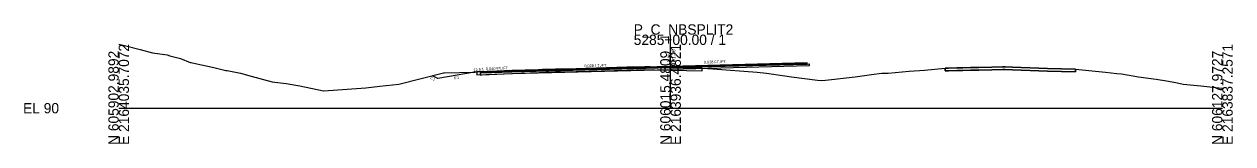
# Model space of a CAD drawing. Extents: x -26 to 1303, y -10 to 12038.
# Drawn here: x -25.7 to 302.8, y 2990.3 to 3022.8 of the extents above; entities that cross this region are included whole.
import ezdxf

# ---------------------------------------------------------------- set-up
doc = ezdxf.new("R2010")
doc.units = 0
for name, color, linetype in [('RD_GPK_XS_Cell', 7, 'Continuous'), ('RD_XS_Base', 7, 'Continuous'), ('RD_XS_ExGround', 7, 'Continuous'), ('RD_XS_ExPaveRet', 7, 'Continuous'), ('RD_XS_Greenside', 7, 'Continuous'), ('RD_XS_Pave', 7, 'Continuous'), ('RD_XS_PaveOvlay_CP', 7, 'Continuous'), ('RD_XS_TieSlope', 7, 'Continuous'), ('RD_XS_TX_Elev_EX', 7, 'Continuous'), ('RD_XS_TX_Elev_PR', 7, 'Continuous'), ('RD_XS_TX_ShdSlope', 7, 'Continuous'), ('RD_XS_TX_Slope', 7, 'Continuous')]:
    doc.layers.add(name, color=color, linetype=linetype)

msp = doc.modelspace()

# ---------------------------------------------------------------- linework, layer by layer
at = {"layer": 'RD_GPK_XS_Cell'}
for p, q in [((150, 3000), (150, 3020)), ((0, 3000), (150, 3000)), ((150, 3000), (300, 3000))]:
    msp.add_line(p, q, dxfattribs=at)
at = {"layer": 'RD_XS_Base'}
for p, q in [((98.73, 3009.59), (98.23, 3009.57)), ((98.23, 3009.57), (98.23, 3009.57)), ((98.23, 3009.57), (98.23, 3009.07)), ((106.83, 3009.92), (98.73, 3009.59)), ((98.73, 3009.59), (98.73, 3009.59)), ((98.73, 3009.09), (106.83, 3009.42)), ((150, 3011.04), (106.83, 3009.92)), ((106.83, 3009.42), (150, 3010.54)), ((138, 3010.73), (138, 3010.73)), ((138, 3010.23), (138, 3010.23)), ((150, 3011.04), (187.66, 3012.02)), ((187.66, 3011.52), (150, 3010.54)), ((150, 3010.54), (150, 3011.2)), ((150, 3011.2), (150, 3011.2)), ((150, 3011.2), (150, 3011.2)), ((150, 3011.2), (150, 3011.04)), ((150, 3011.04), (150, 3011.04)), ((150, 3010.54), (150, 3011.04)), ((150, 3011.04), (150, 3011.04)), ((150, 3011.04), (150, 3011.04)), ((150, 3010.54), (150, 3010.54)), ((174, 3011.66), (174, 3011.66)), ((174, 3011.66), (174, 3011.66)), ((174, 3011.16), (174, 3011.16)), ((174, 3011.16), (174, 3011.16)), ((187.16, 3012.01), (187.16, 3012.01)), ((187.66, 3012.02), (187.66, 3011.52)), ((187.66, 3011.99), (187.66, 3011.99)), ((98.23, 3009.07), (98.73, 3009.09)), ((98.73, 3009.09), (98.73, 3009.09))]:
    msp.add_line(p, q, dxfattribs=at)
at = {"layer": 'RD_XS_ExGround'}
msp.add_lwpolyline([(0, 3017.36), (1.91, 3016.98), (5.88, 3015.95), (9.16, 3015.07), (13.16, 3014.48), (13.88, 3014.25), (16.81, 3013.48), (19.46, 3012.46), (19.74, 3012.39), (20.41, 3012.24), (25.87, 3011.07), (29.15, 3010.2), (29.46, 3010.21), (33.12, 3009.48), (36, 3008.71), (41.73, 3007.12), (45.53, 3006.7), (49.2, 3006.07), (55.65, 3004.71), (55.7, 3004.69), (55.77, 3004.7), (67.14, 3005.51), (70.97, 3005.98), (76.17, 3006.54), (88.27, 3009.57), (88.48, 3009.62), (96.82, 3009.83), (97.37, 3009.85), (97.38, 3009.85), (114.31, 3010.46), (115.19, 3010.48), (116.15, 3010.5), (118.69, 3010.59), (124.37, 3010.74), (138.12, 3011.12), (143.03, 3011.24), (143.04, 3011.22), (143.05, 3011.21), (143.18, 3011.22), (144.49, 3011.22), (145.76, 3011.19), (158.6, 3010.87), (161.53, 3010.71), (173.53, 3009.77), (176.08, 3009.52), (181.07, 3008.8), (182.92, 3008.5), (189.93, 3007.66), (191.01, 3007.51), (192.11, 3007.66), (200.2, 3008.5), (204.6, 3009.12), (207.45, 3009.48), (209.2, 3009.54), (214.85, 3010.06), (219.03, 3010.35), (224.65, 3010.86), (227.84, 3010.96), (230.72, 3011.04), (233.78, 3011.08), (240.24, 3011.23), (240.99, 3011.23), (252.51, 3010.83), (260.05, 3010.59), (268.19, 3009.83), (271.33, 3009.45), (272.56, 3009.33), (277.18, 3008.5), (282.01, 3007.85), (284.79, 3007.45), (287.39, 3006.95), (289.37, 3006.5), (294.12, 3006.06), (299.81, 3005.4), (300, 3005.44)], dxfattribs=at)
at = {"layer": 'RD_XS_ExPaveRet'}
for points in [[(158.6, 3010.87), (158.6, 3010.87), (145.76, 3011.19), (145.76, 3011.19), (144.49, 3011.22), (143.18, 3011.22), (143.18, 3011.22), (143.05, 3011.21), (143.05, 3011.21), (143.04, 3011.22), (143.03, 3011.24), (143.03, 3011.24), (143.03, 3011.24), (138.12, 3011.12), (138.12, 3011.12), (124.37, 3010.74), (124.37, 3010.74), (124.37, 3010.74), (118.69, 3010.59), (118.69, 3010.59), (116.15, 3010.5), (115.19, 3010.48), (114.31, 3010.46), (114.31, 3010.46), (114.31, 3010.46), (97.38, 3009.85), (97.38, 3009.85), (97.38, 3009.85), (97.37, 3009.85), (97.37, 3009.85), (97.37, 3009.85), (97.37, 3009.1), (97.37, 3009.1), (97.38, 3009.1), (97.38, 3009.1), (97.38, 3009.1), (114.31, 3009.71), (114.31, 3009.71), (114.31, 3009.71), (115.19, 3009.73), (116.15, 3009.75), (118.69, 3009.84), (118.69, 3009.84), (124.37, 3009.99), (124.37, 3009.99), (124.37, 3009.99), (138.12, 3010.37), (138.12, 3010.37), (143.03, 3010.49), (143.03, 3010.49), (143.03, 3010.49), (143.04, 3010.47), (143.05, 3010.46), (143.05, 3010.46), (143.18, 3010.47), (143.18, 3010.47), (144.49, 3010.47), (145.76, 3010.44), (145.76, 3010.44), (158.6, 3010.12), (158.6, 3010.12), (158.6, 3010.12), (158.6, 3010.87), (158.6, 3010.87), (158.6, 3010.87)], [(158.6, 3010.87), (145.76, 3011.19), (144.49, 3011.22), (143.18, 3011.22), (143.05, 3011.21), (143.04, 3011.22), (143.03, 3011.24), (138.12, 3011.12), (124.37, 3010.74), (118.69, 3010.59), (116.15, 3010.5), (115.19, 3010.48), (114.31, 3010.46), (97.38, 3009.85), (97.37, 3009.85), (97.37, 3009.85), (97.37, 3009.1), (97.37, 3009.1), (97.38, 3009.1), (114.31, 3009.71), (115.19, 3009.73), (116.15, 3009.75), (118.69, 3009.84), (124.37, 3009.99), (138.12, 3010.37), (143.03, 3010.49), (143.04, 3010.47), (143.05, 3010.46), (143.18, 3010.47), (144.49, 3010.47), (145.76, 3010.44), (158.6, 3010.12), (158.6, 3010.12), (158.6, 3010.87), (158.6, 3010.87)], [(256.3, 3010.71), (260.05, 3010.59), (260.05, 3010.03), (260.05, 3009.84), (256.3, 3009.96), (252.51, 3010.08), (242.92, 3010.41), (240.99, 3010.48), (240.38, 3010.48), (240.24, 3010.48), (237.32, 3010.41), (233.78, 3010.33), (231.53, 3010.3), (229.46, 3010.24), (228.64, 3010.23), (227.84, 3010.21), (225.58, 3010.14), (224.65, 3010.11), (224.65, 3010.11), (224.65, 3010.11), (224.65, 3010.43), (224.65, 3010.86), (224.65, 3010.86), (224.65, 3010.86), (225.58, 3010.89), (227.84, 3010.96), (228.64, 3010.98), (229.46, 3010.99), (231.53, 3011.05), (233.78, 3011.08), (237.32, 3011.16), (240.24, 3011.23), (240.38, 3011.23), (240.99, 3011.23), (242.92, 3011.16), (252.51, 3010.83), (256.3, 3010.71)], [(252.51, 3010.83), (242.92, 3011.16), (240.99, 3011.23), (240.38, 3011.23), (240.24, 3011.23), (237.32, 3011.16), (233.78, 3011.08), (231.53, 3011.05), (229.46, 3010.99), (228.64, 3010.98), (227.84, 3010.96), (225.58, 3010.89), (224.65, 3010.86), (224.65, 3010.86), (224.65, 3010.43), (224.65, 3010.11)], [(224.65, 3010.11), (225.58, 3010.14), (227.84, 3010.21), (228.64, 3010.23), (229.46, 3010.24), (231.53, 3010.3), (233.78, 3010.33), (237.32, 3010.41), (240.24, 3010.48), (240.38, 3010.48), (240.99, 3010.48), (242.92, 3010.41), (252.51, 3010.08), (256.3, 3009.96), (260.05, 3009.84), (260.05, 3010.03), (260.05, 3010.59), (256.3, 3010.71), (252.51, 3010.83)], [(224.65, 3010.11), (224.65, 3010.11)]]:
    msp.add_lwpolyline(points, dxfattribs=at)
at = {"layer": 'RD_XS_Greenside'}
for p, q in [((96.73, 3009.75), (86.73, 3008.08)), ((86.73, 3008.08), (85.27, 3008.82))]:
    msp.add_line(p, q, dxfattribs=at)
at = {"layer": 'RD_XS_Pave'}
for p, q in [((106.83, 3010.24), (98.73, 3009.91)), ((98.73, 3009.75), (106.83, 3010.08)), ((106.83, 3010.08), (98.73, 3009.75)), ((98.73, 3009.59), (106.83, 3009.92)), ((98.73, 3009.91), (98.73, 3009.91)), ((98.73, 3009.91), (98.73, 3009.75)), ((98.73, 3009.75), (98.73, 3009.75)), ((98.73, 3009.75), (98.73, 3009.59)), ((150, 3011.36), (106.83, 3010.24)), ((106.83, 3010.08), (150, 3011.2)), ((150, 3011.2), (106.83, 3010.08)), ((106.83, 3009.92), (150, 3011.04)), ((138, 3011.05), (138, 3011.05)), ((138, 3010.89), (138, 3010.89)), ((138, 3010.89), (138, 3010.89)), ((138, 3010.73), (138, 3010.73)), ((187.16, 3012.32), (150, 3011.36)), ((187.16, 3012.16), (150, 3011.2)), ((150, 3011.2), (187.16, 3012.16)), ((150, 3011.04), (187.16, 3012.01)), ((150, 3011.36), (150, 3011.36)), ((150, 3011.2), (150, 3011.2)), ((150, 3011.2), (150, 3011.2)), ((150, 3011.2), (150, 3011.04)), ((150, 3011.2), (150, 3011.2)), ((150, 3011.04), (150, 3011.2)), ((150, 3011.2), (150, 3011.2)), ((150, 3011.2), (150, 3011.2)), ((150, 3011.04), (150, 3011.04)), ((150, 3011.04), (150, 3011.04)), ((174, 3011.98), (174, 3011.98)), ((174, 3011.98), (174, 3011.98)), ((174, 3011.82), (174, 3011.82)), ((174, 3011.82), (174, 3011.82)), ((174, 3011.82), (174, 3011.82)), ((174, 3011.82), (174, 3011.82)), ((174, 3011.66), (174, 3011.66)), ((174, 3011.66), (174, 3011.66)), ((187.16, 3012.16), (187.16, 3012.32)), ((187.16, 3012.32), (187.16, 3012.32)), ((187.16, 3012.01), (187.16, 3012.16)), ((187.16, 3012.16), (187.16, 3012.16))]:
    msp.add_line(p, q, dxfattribs=at)
at = {"layer": 'RD_XS_PaveOvlay_CP'}
for p, q in [((106.83, 3010.24), (98.73, 3009.91)), ((150, 3011.36), (106.83, 3010.24)), ((138, 3011.05), (138, 3011.05)), ((187.16, 3012.32), (150, 3011.36)), ((150, 3011.36), (150, 3011.36)), ((174, 3011.98), (174, 3011.98)), ((174, 3011.98), (174, 3011.98))]:
    msp.add_line(p, q, dxfattribs=at)
at = {"layer": 'RD_XS_TieSlope'}
msp.add_line((98.73, 3009.91), (96.73, 3009.75), dxfattribs=at)

# ---------------------------------------------------------------- texts
at = {"layer": 'RD_GPK_XS_Cell'}
for s, p in [('P_C_NBSPLIT2', (140, 3020)), ('5285+00.00 / 1', (140, 3017.2)), ('EL 90', (-26, 2998.6))]:
    msp.add_text(s, height=2.8, dxfattribs=at).set_placement(p)
for s, p in [('E 2164035.7072', (2.8, 2990)), ('E 2163936.4821', (152.8, 2990)), ('E 2163837.2571', (302.8, 2990)), ('N 605902.9892', (0, 2990)), ('N 606015.4809', (150, 2990)), ('N 606127.9727', (300, 2990))]:
    msp.add_text(s, height=2.8, rotation=90, dxfattribs=at).set_placement(p)
at = {"layer": 'RD_XS_TX_Elev_EX'}
msp.add_text('101.09', height=0.6, rotation=90, dxfattribs=at).set_placement((149.68, 3012.04))
at = {"layer": 'RD_XS_TX_Elev_PR'}
msp.add_text('101.36', height=1, rotation=90, dxfattribs=at).set_placement((151.32, 3011.78))
at = {"layer": 'RD_XS_TX_ShdSlope'}
msp.add_text('12.5:1', height=0.75, rotation=4.5739, dxfattribs=at).set_placement((96.44, 3010.02))
at = {"layer": 'RD_XS_TX_Slope'}
for s, rotation, p in [('0.028 FT./FT.', 1.6039, (159.06, 3012.11)), ('0.040 FT./FT.', 2.2906, (99.83, 3010.32)), ('0.028 FT./FT.', 1.6039, (126.57, 3011.12)), ('2:1', 333.4349, (84.55, 3008.08)), ('6:1', 9.4642, (91.17, 3007.84))]:
    msp.add_text(s, height=0.75, rotation=rotation, dxfattribs=at).set_placement(p)

doc.saveas('drawing.dxf')
